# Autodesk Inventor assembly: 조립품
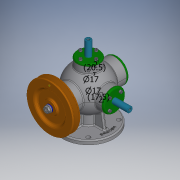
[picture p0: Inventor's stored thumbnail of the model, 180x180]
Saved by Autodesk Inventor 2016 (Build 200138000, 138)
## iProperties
Created: 2019-11
Part Number: 조립품
Material: 일반
Document SubType Name: Assembly
Designer: user
Author: user
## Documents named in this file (17)
- C:\Users\user\Desktop\391120V1005\조립품.iam
- C:\Users\user\Desktop\391120V1005\V-벨트풀리.ipt
- C:\Users\user\Desktop\391120V1005\너트 M8x1.ipt
- C:\Users\user\Desktop\391120V1005\뒤커버.ipt
- C:\Users\user\Desktop\391120V1005\베어링 6202.ipt
- C:\Users\user\Desktop\391120V1005\본체.ipt
- C:\Users\user\Desktop\391120V1005\본체커버.ipt
- C:\Users\user\Desktop\391120V1005\볼트 M4.ipt
- C:\Users\user\Desktop\391120V1005\스프링1.ipt
- C:\Users\user\Desktop\391120V1005\스프링2.ipt
- C:\Users\user\Desktop\391120V1005\슬라이드 커버.ipt
- C:\Users\user\Desktop\391120V1005\슬라이드.ipt
- C:\Users\user\Desktop\391120V1005\앞커버.ipt
- C:\Users\user\Desktop\391120V1005\오일 실.ipt
- C:\Users\user\Desktop\391120V1005\와셔 8x17.ipt
- C:\Users\user\Desktop\391120V1005\축.ipt
- C:\Users\user\Desktop\391120V1005\키 4x4.ipt
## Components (1 placed, 1 different names)
1. V-벨트풀리:1
